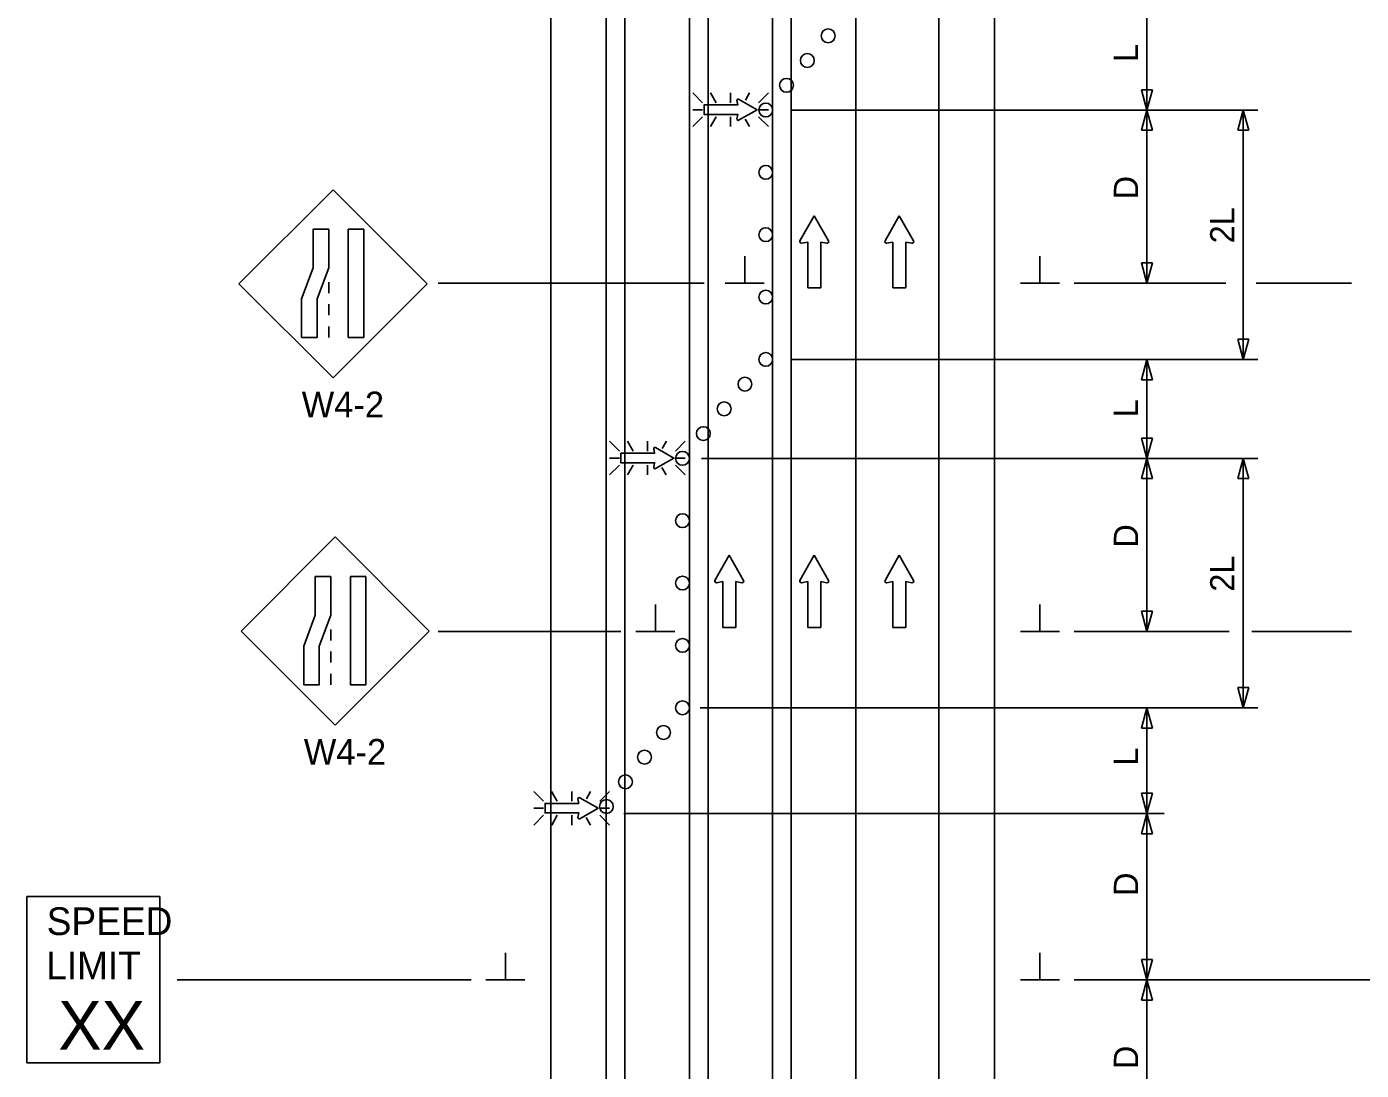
# Model space of a CAD drawing. Extents: x 16734 to 18475, y 5704 to 7011.
# Drawn here: x 16744.6 to 17129.7, y 6335.5 to 6636.8 of the extents above; entities that cross this region are included whole.
import ezdxf

# ---------------------------------------------------------------- set-up
doc = ezdxf.new("R2010")
doc.units = 0
for name, color, linetype in [('ALI_LEGAL_EX', 7, 'Continuous'), ('MT_SCRATCH_LEVEL_E', 7, 'Continuous'), ('PAVT_EDGE_EX', 7, 'Continuous'), ('TRAFFIC_SIGNS_PR', 7, 'Continuous'), ('TYPICAL_TEXT_DIMEN_PR', 7, 'Continuous')]:
    doc.layers.add(name, color=color, linetype=linetype)

msp = doc.modelspace()

# ---------------------------------------------------------------- linework, layer by layer
at = {"layer": 'ALI_LEGAL_EX'}
for p, q in [((16917.23, 7011.11), (16917.23, 6181.92)), ((16941.23, 7011.11), (16941.23, 6181.92)), ((16965.23, 7011.11), (16965.23, 6181.92)), ((16965.23, 7011.11), (16965.23, 6181.92)), ((16935.85, 6875.49), (16935.85, 6046.3)), ((16959.85, 6875.49), (16959.85, 6046.3)), ((16983.85, 6875.49), (16983.85, 6046.3)), ((16983.85, 6875.49), (16983.85, 6046.3))]:
    msp.add_line(p, q, dxfattribs=at)
for points in [[(16935.85, 6575.49), (16935.85, 6550.49)], [(16959.85, 6575.49), (16959.85, 6550.49)], [(16983.85, 6575.49), (16983.85, 6550.49)], [(16935.85, 6475.49), (16935.85, 6450.49)], [(16959.85, 6475.49), (16959.85, 6450.49)], [(16983.85, 6475.49), (16983.85, 6450.49)], [(16935.85, 6375.49), (16935.85, 6350.49)], [(16959.85, 6375.49), (16959.85, 6350.49)], [(16983.85, 6375.49), (16983.85, 6350.49)]]:
    msp.add_lwpolyline(points, dxfattribs=at)
at = {"layer": 'MT_SCRATCH_LEVEL_E'}
for p, q in [((16971.82, 6582.26), (16967.71, 6575.02)), ((16971.82, 6582.26), (16967.71, 6575.02)), ((16975.97, 6575.02), (16971.82, 6582.26)), ((16975.97, 6575.02), (16971.82, 6582.26)), ((16996.38, 6582.26), (16992.27, 6575.02)), ((16996.38, 6582.26), (16992.27, 6575.02)), ((17000.53, 6575.02), (16996.38, 6582.26)), ((17000.53, 6575.02), (16996.38, 6582.26)), ((16968.19, 6574.34), (16969.97, 6574.65)), ((16968.19, 6574.34), (16969.97, 6574.65)), ((16969.97, 6574.65), (16969.97, 6561.39)), ((16969.97, 6574.65), (16969.97, 6561.39)), ((16973.71, 6561.39), (16973.71, 6574.65)), ((16973.71, 6574.65), (16975.49, 6574.34)), ((16973.71, 6561.39), (16973.71, 6574.65)), ((16973.71, 6574.65), (16975.49, 6574.34)), ((16992.75, 6574.34), (16994.53, 6574.65)), ((16992.75, 6574.34), (16994.53, 6574.65)), ((16994.53, 6574.65), (16994.53, 6561.39)), ((16994.53, 6574.65), (16994.53, 6561.39)), ((16998.27, 6561.39), (16998.27, 6574.65)), ((16998.27, 6574.65), (17000.05, 6574.34)), ((16998.27, 6561.39), (16998.27, 6574.65)), ((16998.27, 6574.65), (17000.05, 6574.34)), ((16969.97, 6561.39), (16973.71, 6561.39)), ((16969.97, 6561.39), (16973.71, 6561.39)), ((16994.53, 6561.39), (16998.27, 6561.39)), ((16994.53, 6561.39), (16998.27, 6561.39)), ((16947.29, 6484.22), (16943.18, 6476.98)), ((16947.29, 6484.22), (16943.18, 6476.98)), ((16951.44, 6476.98), (16947.29, 6484.22)), ((16951.44, 6476.98), (16947.29, 6484.22)), ((16971.82, 6484.22), (16967.71, 6476.98)), ((16971.82, 6484.22), (16967.71, 6476.98)), ((16975.97, 6476.98), (16971.82, 6484.22)), ((16975.97, 6476.98), (16971.82, 6484.22)), ((16996.38, 6484.22), (16992.27, 6476.98)), ((16996.38, 6484.22), (16992.27, 6476.98)), ((17000.53, 6476.98), (16996.38, 6484.22)), ((17000.53, 6476.98), (16996.38, 6484.22)), ((16943.67, 6476.29), (16945.44, 6476.61)), ((16943.67, 6476.29), (16945.44, 6476.61)), ((16945.44, 6476.61), (16945.44, 6463.35)), ((16945.44, 6476.61), (16945.44, 6463.35)), ((16949.18, 6463.35), (16949.18, 6476.61)), ((16949.18, 6476.61), (16950.96, 6476.29)), ((16949.18, 6463.35), (16949.18, 6476.61)), ((16949.18, 6476.61), (16950.96, 6476.29)), ((16968.19, 6476.29), (16969.97, 6476.61)), ((16968.19, 6476.29), (16969.97, 6476.61)), ((16969.97, 6476.61), (16969.97, 6463.35)), ((16969.97, 6476.61), (16969.97, 6463.35)), ((16973.71, 6463.35), (16973.71, 6476.61)), ((16973.71, 6476.61), (16975.49, 6476.29)), ((16973.71, 6463.35), (16973.71, 6476.61)), ((16973.71, 6476.61), (16975.49, 6476.29)), ((16992.75, 6476.29), (16994.53, 6476.61)), ((16992.75, 6476.29), (16994.53, 6476.61)), ((16994.53, 6476.61), (16994.53, 6463.35)), ((16994.53, 6476.61), (16994.53, 6463.35)), ((16998.27, 6463.35), (16998.27, 6476.61)), ((16998.27, 6476.61), (17000.05, 6476.29)), ((16998.27, 6463.35), (16998.27, 6476.61)), ((16998.27, 6476.61), (17000.05, 6476.29)), ((16945.44, 6463.35), (16949.18, 6463.35)), ((16945.44, 6463.35), (16949.18, 6463.35)), ((16969.97, 6463.35), (16973.71, 6463.35)), ((16969.97, 6463.35), (16973.71, 6463.35)), ((16994.53, 6463.35), (16998.27, 6463.35)), ((16994.53, 6463.35), (16998.27, 6463.35))]:
    msp.add_line(p, q, dxfattribs=at)
for centre, start, end in [((16968.12, 6574.79), 150.4248, 279.9638), ((16968.12, 6574.79), 150.4248, 279.9638), ((16975.56, 6574.8), 260.0362, 29.7731), ((16975.56, 6574.8), 260.0362, 29.7731), ((16992.68, 6574.79), 150.4248, 279.9638), ((16992.68, 6574.79), 150.4248, 279.9638), ((17000.12, 6574.8), 260.0362, 29.7731), ((17000.12, 6574.8), 260.0362, 29.7731), ((16943.59, 6476.75), 150.4248, 279.9638), ((16943.59, 6476.75), 150.4248, 279.9638), ((16951.03, 6476.75), 260.0362, 29.7731), ((16951.03, 6476.75), 260.0362, 29.7731), ((16968.12, 6476.75), 150.4248, 279.9638), ((16968.12, 6476.75), 150.4248, 279.9638), ((16975.56, 6476.75), 260.0362, 29.7731), ((16975.56, 6476.75), 260.0362, 29.7731), ((16992.68, 6476.75), 150.4248, 279.9638), ((16992.68, 6476.75), 150.4248, 279.9638), ((17000.12, 6476.75), 260.0362, 29.7731), ((17000.12, 6476.75), 260.0362, 29.7731)]:
    msp.add_arc(centre, 0.463, start, end, dxfattribs=at)
at = {"layer": 'PAVT_EDGE_EX'}
for p, q in [((16911.85, 6920.73), (16911.85, 6024.13)), ((17007.85, 6920.73), (17007.85, 6024.13)), ((17023.85, 6920.73), (17023.85, 6024.13)), ((16895.85, 6869.12), (16895.85, 6024.13))]:
    msp.add_line(p, q, dxfattribs=at)
at = {"layer": 'TRAFFIC_SIGNS_PR'}
for p, q in [((16939.63, 6614.87), (16936.81, 6617.69)), ((16941.93, 6617.69), (16943.56, 6614.87)), ((16947.72, 6614.87), (16947.72, 6617.69)), ((16953.18, 6617.69), (16951.98, 6615.6)), ((16958.62, 6617.69), (16955.8, 6614.87)), ((16939.63, 6612.84), (16936.81, 6612.84)), ((16939.63, 6610.81), (16936.81, 6607.99)), ((16943.58, 6610.81), (16941.95, 6607.99)), ((16947.72, 6610.81), (16947.72, 6607.99)), ((16951.9, 6610.17), (16953.16, 6607.99)), ((16955.8, 6612.84), (16958.62, 6612.84)), ((16958.62, 6607.99), (16955.8, 6610.81)), ((16832.98, 6589.77), (16805.83, 6562.62)), ((16860.14, 6562.62), (16832.98, 6589.77)), ((16831.74, 6563.11), (16831.74, 6559.91)), ((16805.83, 6562.62), (16832.98, 6535.47)), ((16832.98, 6535.47), (16860.14, 6562.62)), ((16831.74, 6556.71), (16831.74, 6553.51)), ((16831.74, 6550.31), (16831.74, 6547.11)), ((16915.63, 6514.31), (16912.81, 6517.13)), ((16917.93, 6517.13), (16919.56, 6514.31)), ((16923.72, 6514.31), (16923.72, 6517.13)), ((16929.18, 6517.13), (16927.98, 6515.03)), ((16934.62, 6517.13), (16931.8, 6514.31)), ((16915.63, 6512.28), (16912.81, 6512.28)), ((16915.63, 6510.24), (16912.81, 6507.42)), ((16919.58, 6510.24), (16917.95, 6507.42)), ((16923.72, 6510.24), (16923.72, 6507.42)), ((16927.9, 6509.61), (16929.16, 6507.42)), ((16931.8, 6512.28), (16934.62, 6512.28)), ((16934.62, 6507.43), (16931.8, 6510.24)), ((16833.59, 6489.5), (16806.44, 6462.34)), ((16860.74, 6462.34), (16833.59, 6489.5)), ((16832.34, 6462.84), (16832.34, 6459.64)), ((16806.44, 6462.34), (16833.59, 6435.19)), ((16833.59, 6435.19), (16860.74, 6462.34)), ((16832.34, 6456.44), (16832.34, 6453.24)), ((16832.34, 6450.04), (16832.34, 6446.84)), ((16893.76, 6413.22), (16890.94, 6416.04)), ((16896.06, 6416.04), (16897.69, 6413.22)), ((16901.85, 6413.22), (16901.85, 6416.04)), ((16907.31, 6416.04), (16906.11, 6413.95)), ((16912.75, 6416.04), (16909.93, 6413.22)), ((16893.76, 6411.19), (16890.94, 6411.19)), ((16893.76, 6409.16), (16890.94, 6406.34)), ((16897.71, 6409.16), (16896.08, 6406.34)), ((16901.85, 6409.16), (16901.85, 6406.34)), ((16909.93, 6411.19), (16912.75, 6411.19)), ((16912.75, 6406.34), (16909.93, 6409.16)), ((16906.03, 6408.52), (16907.29, 6406.34)), ((16744.58, 6385.72), (16782.98, 6385.72)), ((16744.58, 6337.72), (16744.58, 6385.72)), ((16782.98, 6337.72), (16782.98, 6385.72)), ((16744.58, 6337.72), (16782.98, 6337.72))]:
    msp.add_line(p, q, dxfattribs=at)
for points in [[(16949.54, 6615.52), (16949.77, 6614.23), (16940.05, 6614.23), (16940.05, 6611.48), (16949.77, 6611.48), (16949.54, 6610.18)], [(16950.04, 6609.82), (16955.35, 6612.84), (16950.04, 6615.88)], [(16925.54, 6514.96), (16925.77, 6513.66), (16916.05, 6513.66), (16916.05, 6510.92), (16925.77, 6510.92), (16925.54, 6509.61)], [(16926.04, 6509.26), (16931.35, 6512.28), (16926.04, 6515.32)], [(16903.67, 6413.87), (16903.9, 6412.57), (16894.18, 6412.57), (16894.18, 6409.83), (16903.9, 6409.83), (16903.67, 6408.53)], [(16904.17, 6408.17), (16909.48, 6411.19), (16904.17, 6414.23)]]:
    msp.add_lwpolyline(points, dxfattribs=at)
for points in [[(16831.74, 6578.36), (16831.74, 6567.17), (16828.39, 6558.29), (16828.39, 6547.11), (16823.9, 6547.11), (16823.9, 6558.29), (16827.24, 6567.17), (16827.24, 6578.36)], [(16841.87, 6578.36), (16841.87, 6547.11), (16837.38, 6547.11), (16837.38, 6578.36)], [(16832.34, 6478.08), (16832.34, 6466.9), (16829, 6458.02), (16829, 6446.84), (16824.51, 6446.84), (16824.51, 6458.02), (16827.85, 6466.9), (16827.85, 6478.08)], [(16842.48, 6478.08), (16842.48, 6446.84), (16837.99, 6446.84), (16837.99, 6478.08)]]:
    msp.add_lwpolyline(points, close=True, dxfattribs=at)
for centre in [(16975.85, 6634.19), (16969.85, 6627.05), (16963.85, 6619.91), (16957.85, 6612.77), (16957.85, 6612.77), (16957.85, 6594.77), (16957.85, 6576.77), (16957.85, 6558.77), (16957.85, 6558.77), (16957.85, 6540.77), (16951.85, 6533.63), (16945.85, 6526.49), (16939.85, 6519.35), (16933.85, 6512.2), (16933.85, 6494.2), (16933.85, 6476.2), (16933.85, 6458.2), (16933.85, 6440.2), (16928.36, 6433.07), (16922.86, 6425.94), (16917.36, 6418.82), (16911.87, 6411.69)]:
    msp.add_circle(centre, 2, dxfattribs=at)
for centre, start, end in [((16949.88, 6615.58), 61.4833, 189.9593), ((16949.88, 6610.12), 170.7308, 298.8916), ((16925.88, 6515.02), 61.4833, 189.9593), ((16925.88, 6509.56), 170.7308, 298.8916), ((16904.01, 6413.93), 61.4833, 189.9593), ((16904.01, 6408.47), 170.7308, 298.8916)]:
    msp.add_arc(centre, 0.341, start, end, dxfattribs=at)
at = {"layer": 'TYPICAL_TEXT_DIMEN_PR'}
for p, q in [((17067.85, 6612.77), (17067.85, 6643.33)), ((17067.85, 6612.77), (17066.28, 6618.63)), ((17066.28, 6618.63), (17067.85, 6618.63)), ((17067.85, 6618.63), (17069.42, 6618.63)), ((17069.42, 6618.63), (17067.85, 6612.77)), ((17099.9, 6612.77), (16965.47, 6612.77)), ((17066.28, 6606.91), (17067.85, 6612.77)), ((17067.85, 6612.77), (17067.85, 6562.77)), ((17067.85, 6612.77), (17069.42, 6606.91)), ((17094.09, 6606.91), (17095.66, 6612.77)), ((17095.66, 6612.77), (17095.66, 6540.77)), ((17095.66, 6612.77), (17097.23, 6606.91)), ((17067.85, 6606.91), (17066.28, 6606.91)), ((17069.42, 6606.91), (17067.85, 6606.91)), ((17095.66, 6606.91), (17094.09, 6606.91)), ((17097.23, 6606.91), (17095.66, 6606.91)), ((16951.78, 6562.77), (16951.78, 6570.55)), ((17036.98, 6562.77), (17036.98, 6570.55)), ((17067.85, 6562.77), (17066.28, 6568.63)), ((17066.28, 6568.63), (17067.85, 6568.63)), ((17067.85, 6568.63), (17069.42, 6568.63)), ((17069.42, 6568.63), (17067.85, 6562.77)), ((17095.66, 6567.64), (17095.66, 6563.87)), ((16863.32, 6562.77), (16940.05, 6562.77)), ((16957.41, 6562.77), (16946.16, 6562.77)), ((17042.6, 6562.77), (17031.35, 6562.77)), ((17090.66, 6562.77), (17046.85, 6562.77)), ((17126.85, 6562.77), (17099.41, 6562.77)), ((17095.66, 6540.77), (17094.09, 6546.63)), ((17094.09, 6546.63), (17095.66, 6546.63)), ((17095.66, 6546.63), (17097.23, 6546.63)), ((17097.23, 6546.63), (17095.66, 6540.77)), ((16965.47, 6540.77), (17099.9, 6540.77)), ((17066.28, 6534.91), (17067.85, 6540.77)), ((17067.85, 6512.2), (17067.85, 6540.77)), ((17067.85, 6540.77), (17069.42, 6534.91)), ((17067.85, 6534.91), (17066.28, 6534.91)), ((17069.42, 6534.91), (17067.85, 6534.91)), ((17067.85, 6512.2), (17066.28, 6518.07)), ((17066.28, 6518.07), (17067.85, 6518.07)), ((17067.85, 6518.07), (17069.42, 6518.07)), ((17069.42, 6518.07), (17067.85, 6512.2)), ((16939.3, 6512.2), (17099.9, 6512.2)), ((17066.28, 6506.34), (17067.85, 6512.2)), ((17067.85, 6512.2), (17067.85, 6462.2)), ((17067.85, 6512.2), (17069.42, 6506.34)), ((17094.09, 6506.34), (17095.66, 6512.2)), ((17095.66, 6512.2), (17097.23, 6506.34)), ((17095.66, 6512.2), (17095.66, 6440.2)), ((17067.85, 6506.34), (17066.28, 6506.34)), ((17069.42, 6506.34), (17067.85, 6506.34)), ((17095.66, 6506.34), (17094.09, 6506.34)), ((17097.23, 6506.34), (17095.66, 6506.34)), ((16926, 6462.2), (16926, 6469.99)), ((17036.98, 6462.2), (17036.98, 6469.99)), ((17067.85, 6462.2), (17066.28, 6468.07)), ((17066.28, 6468.07), (17067.85, 6468.07)), ((17067.85, 6468.07), (17069.42, 6468.07)), ((17069.42, 6468.07), (17067.85, 6462.2)), ((16863.32, 6462.2), (16916.08, 6462.2)), ((16931.63, 6462.2), (16920.38, 6462.2)), ((17042.6, 6462.2), (17031.35, 6462.2)), ((17091.54, 6462.2), (17046.85, 6462.2)), ((17126.85, 6462.2), (17098.1, 6462.2)), ((17095.66, 6440.2), (17094.09, 6446.07)), ((17094.09, 6446.07), (17095.66, 6446.07)), ((17095.66, 6446.07), (17097.23, 6446.07)), ((17097.23, 6446.07), (17095.66, 6440.2)), ((16938.96, 6440.2), (17099.9, 6440.2)), ((17066.28, 6434.34), (17067.85, 6440.2)), ((17067.85, 6409.64), (17067.85, 6440.2)), ((17067.85, 6440.2), (17069.42, 6434.34)), ((17067.85, 6434.34), (17066.28, 6434.34)), ((17069.42, 6434.34), (17067.85, 6434.34)), ((17067.85, 6409.64), (17066.28, 6415.5)), ((17066.28, 6415.5), (17067.85, 6415.5)), ((17067.85, 6415.5), (17069.42, 6415.5)), ((17069.42, 6415.5), (17067.85, 6409.64)), ((16916.86, 6409.64), (17072.85, 6409.64)), ((17066.28, 6403.78), (17067.85, 6409.64)), ((17067.85, 6409.64), (17067.85, 6361.65)), ((17067.85, 6409.64), (17069.42, 6403.78)), ((17067.85, 6403.78), (17066.28, 6403.78)), ((17069.42, 6403.78), (17067.85, 6403.78)), ((16882.73, 6361.65), (16882.73, 6369.43)), ((17036.98, 6361.65), (17036.98, 6369.43)), ((17067.85, 6361.65), (17066.28, 6367.51)), ((17066.28, 6367.51), (17067.85, 6367.51)), ((17067.85, 6367.51), (17069.42, 6367.51)), ((17069.42, 6367.51), (17067.85, 6361.65)), ((16787.96, 6361.65), (16872.85, 6361.65)), ((16877.1, 6361.65), (16888.35, 6361.65)), ((17042.6, 6361.65), (17031.35, 6361.65)), ((17160.01, 6361.65), (17046.85, 6361.65)), ((17066.28, 6355.79), (17067.85, 6361.65)), ((17067.85, 6361.65), (17067.85, 6311.65)), ((17067.85, 6361.65), (17069.42, 6355.79)), ((17067.85, 6355.79), (17066.28, 6355.79)), ((17069.42, 6355.79), (17067.85, 6355.79))]:
    msp.add_line(p, q, dxfattribs=at)

# ---------------------------------------------------------------- texts
at = {"layer": 'TRAFFIC_SIGNS_PR'}
for s, height, p in [('W4-2', 7.44, (16823.94, 6524.03)), ('W4-2', 7.44, (16824.55, 6423.75)), ('SPEED', 8, (16750.35, 6374.58)), ('LIMIT', 8, (16750.19, 6361.78)), ('XX', 14.031, (16753.69, 6341.48))]:
    msp.add_text(s, height=height, dxfattribs=at).set_placement(p)
at = {"layer": 'TYPICAL_TEXT_DIMEN_PR'}
for s, p in [('L', (17065.3, 6626.62)), ('D', (17065.3, 6586.99)), ('2L', (17093.1, 6574.27)), ('L', (17065.3, 6524.06)), ('D', (17065.3, 6486.42)), ('2L', (17093.1, 6473.71)), ('L', (17065.3, 6423.5)), ('D', (17065.3, 6385.87)), ('D', (17065.3, 6335.87))]:
    msp.add_text(s, height=7, rotation=90, dxfattribs=at).set_placement(p)

doc.saveas('drawing.dxf')
